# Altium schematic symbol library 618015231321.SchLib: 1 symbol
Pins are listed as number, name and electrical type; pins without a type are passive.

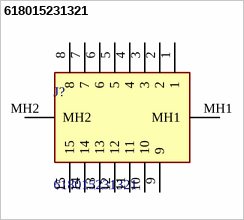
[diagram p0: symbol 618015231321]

## 618015231321
designator J?
Wurth Elektronik 618 Series 2.77 mm, 2.84 mm Pitch 15 Way Right Angle Through Hole Mount PCB D-sub Connector, Socket; Geometry.Height: 12.85mm
footprint 618015231321
pins: 1, 2, 3, 4, 5, 6, 7, 8, 9, 10, 11, 12, 13, 14, 15, MH1, MH2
